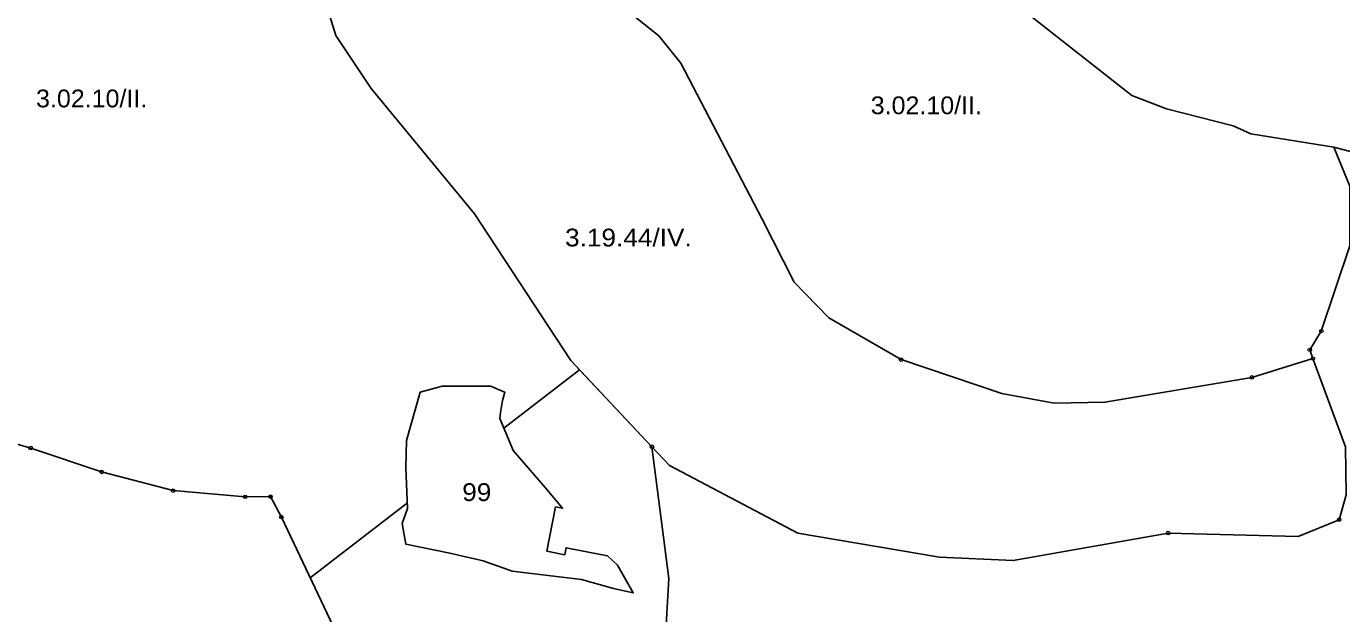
# Model space of a CAD drawing. Extents: x -650455 to -642254, y -1075222 to -1066610.
# Drawn here: x -645923 to -645184, y -1070807 to -1070477 of the extents above; entities that cross this region are included whole.
import ezdxf
from ezdxf.enums import TextEntityAlignment as Align

# ---------------------------------------------------------------- set-up
doc = ezdxf.new("R2010")
doc.units = 0
doc.header["$LTSCALE"] = 4
doc.header["$PDMODE"] = 32
doc.header["$PDSIZE"] = 2
for name, color, linetype, lineweight in [('1', 7, 'Continuous', 25), ('11', 7, 'Continuous', 13), ('12', 7, 'Continuous', 13), ('14', 7, 'Continuous', 13)]:
    doc.layers.add(name, color=color, linetype=linetype, lineweight=lineweight)
doc.layers.add('2', color=7, linetype='Continuous')

msp = doc.modelspace()

# ---------------------------------------------------------------- linework, layer by layer
at = {"layer": '1'}
for points in [[(-645696.21, -1070233.478), (-645696.21, -1070244.446), (-645693.219, -1070253.691), (-645689.807, -1070258.381), (-645677.134, -1070272.424), (-645674.491, -1070275.223), (-645637.482, -1070290.618), (-645562.376, -1070313.01), (-645530.032, -1070322.029), (-645499.088, -1070345.198), (-645474.208, -1070360.748), (-645449.328, -1070376.453), (-645424.604, -1070393.714), (-645420.219, -1070400.367), (-645417, -1070402.501), (-645403, -1070418.001), (-645378, -1070455.501), (-645302, -1070515.501), (-645282.5, -1070523), (-645245, -1070532.501), (-645235, -1070537.001), (-645188.5, -1070544.501), (-645179.5, -1070566.5)], [(-644777, -1070514), (-644832, -1070537.001), (-644888.5, -1070557.001), (-644982, -1070577.501), (-645008.5, -1070579.5), (-645087, -1070571), (-645188.5, -1070544.501), (-645235, -1070537.001), (-645245, -1070532.501), (-645282.5, -1070523), (-645302, -1070515.501), (-645378, -1070455.501), (-645403, -1070418.001), (-645417, -1070402.501), (-645420.219, -1070400.367), (-645424.604, -1070393.714), (-645449.328, -1070376.453), (-645474.208, -1070360.748)], [(-645763.626, -1070420.193), (-645769.807, -1070414.012), (-645749.009, -1070481.878), (-645729, -1070511.501), (-645671, -1070582), (-645617, -1070664.5), (-645571.435, -1070712.939), (-645562, -1070787.001), (-645566, -1070859), (-645576.5, -1070881.501), (-645600.5, -1070904.001), (-645607.5, -1070909.001), (-645646.5, -1070921.501), (-645665, -1070920), (-645678.5, -1070914.5), (-645700.5, -1070899.5), (-645723, -1070872.001), (-645779.5, -1070752.5), (-645785.632, -1070741.019), (-645799.865, -1070741.1), (-645840.313, -1070737.642), (-645880.438, -1070727.108), (-645920.242, -1070713.679), (-645927.962, -1070711.588)], [(-645749.009, -1070481.878), (-645769.807, -1070414.012)], [(-645179.5, -1070600), (-645195.5, -1070648), (-645202, -1070658.501), (-645200.205, -1070663.392), (-645234.5, -1070674.001), (-645317, -1070688), (-645345.5, -1070688.5), (-645375, -1070683.001), (-645431.5, -1070664), (-645472, -1070640.5), (-645491.5, -1070620.501), (-645509.5, -1070585.001), (-645555.128, -1070497.341), (-645567.5, -1070482), (-645607.333, -1070449.913), (-645628.962, -1070442.703), (-645656.783, -1070418.36)], [(-645607.333, -1070449.913), (-645567.5, -1070482), (-645555.128, -1070497.341), (-645509.5, -1070585.001), (-645491.5, -1070620.501), (-645472, -1070640.5), (-645431.5, -1070664), (-645375, -1070683.001), (-645345.5, -1070688.5), (-645317, -1070688), (-645234.5, -1070674.001), (-645200.205, -1070663.392), (-645182, -1070713)], [(-645181.5, -1070740), (-645185.5, -1070754), (-645208.5, -1070763.501), (-645281.5, -1070761.5), (-645368.5, -1070777), (-645410, -1070775.001), (-645489.5, -1070761.5), (-645561.5, -1070723.501), (-645571.435, -1070712.939), (-645617, -1070664.5), (-645671, -1070582), (-645729, -1070511.501), (-645749.009, -1070481.878)], [(-645566, -1070859), (-645562, -1070787.001), (-645571.435, -1070712.939), (-645561.5, -1070723.501), (-645489.5, -1070761.5), (-645410, -1070775.001), (-645368.5, -1070777), (-645281.5, -1070761.5), (-645208.5, -1070763.501), (-645185.5, -1070754), (-645181.5, -1070740), (-645182, -1070713), (-645200.205, -1070663.392), (-645202, -1070658.501), (-645195.5, -1070648), (-645179.5, -1070600), (-645179.5, -1070566.5), (-645188.5, -1070544.501), (-645087, -1070571), (-645008.5, -1070579.5), (-644982, -1070577.501), (-644888.5, -1070557.001), (-644832, -1070537.001), (-644777, -1070514)], [(-645927.962, -1070711.588), (-645920.242, -1070713.679), (-645880.438, -1070727.108), (-645840.313, -1070737.642)], [(-645840.313, -1070737.642), (-645799.865, -1070741.1), (-645785.632, -1070741.019), (-645779.5, -1070752.5), (-645723, -1070872.001)]]:
    msp.add_lwpolyline(points, dxfattribs=at)
for points in [[(-645631.348, -1070735.807), (-645621.58, -1070747.558), (-645625.53, -1070746.79), (-645630.39, -1070771.751), (-645620.35, -1070773.691), (-645619.59, -1070769.75), (-645617.65, -1070770.131), (-645601.26, -1070773.33), (-645598.31, -1070773.9), (-645596.319, -1070774.289), (-645590.68, -1070779.525), (-645581.869, -1070795.114), (-645593.052, -1070792.742), (-645611.014, -1070787.659), (-645649.987, -1070782.914), (-645666.254, -1070777.153), (-645684.894, -1070772.747), (-645709.633, -1070767.664), (-645711.667, -1070756.141), (-645708.617, -1070747.669), (-645709.633, -1070724.623), (-645709.294, -1070709.373), (-645701.5, -1070682.261), (-645689.299, -1070678.872), (-645661.848, -1070678.872), (-645660.211, -1070679.584), (-645660.21, -1070679.591), (-645655.86, -1070681.476), (-645654.054, -1070682.261), (-645655.409, -1070687.006), (-645656.426, -1070693.784), (-645656.765, -1070697.173), (-645650.141, -1070713.131), (-645650.14, -1070713.14), (-645649.309, -1070715.132)], [(-645631.348, -1070735.807), (-645649.309, -1070715.132), (-645650.14, -1070713.14), (-645650.141, -1070713.131), (-645656.765, -1070697.173), (-645656.426, -1070693.784), (-645655.409, -1070687.006), (-645654.054, -1070682.261), (-645655.86, -1070681.476), (-645660.21, -1070679.591), (-645660.211, -1070679.584), (-645661.848, -1070678.872), (-645689.299, -1070678.872), (-645701.5, -1070682.261), (-645709.294, -1070709.373), (-645709.633, -1070724.623), (-645708.617, -1070747.669), (-645711.667, -1070756.141), (-645709.633, -1070767.664), (-645684.894, -1070772.747), (-645666.254, -1070777.153), (-645649.987, -1070782.914), (-645611.014, -1070787.659), (-645593.052, -1070792.742), (-645581.869, -1070795.114), (-645590.68, -1070779.525), (-645596.319, -1070774.289), (-645598.31, -1070773.9), (-645601.26, -1070773.33), (-645617.65, -1070770.131), (-645619.59, -1070769.75), (-645620.35, -1070773.691), (-645630.39, -1070771.751), (-645625.53, -1070746.79), (-645621.58, -1070747.558)]]:
    msp.add_lwpolyline(points, close=True, dxfattribs=at)
at = {"layer": '11'}
for p, q in [((-645840.313, -1070737.642), (-645880.438, -1070727.108)), ((-645779.5, -1070752.5), (-645785.632, -1070741.019)), ((-645723, -1070872.001), (-645779.5, -1070752.5))]:
    msp.add_line(p, q, dxfattribs=at)
for points in [[(-644684, -1070421), (-644702.5, -1070450), (-644728.5, -1070479.001), (-644777, -1070514), (-644832, -1070537.001), (-644888.5, -1070557.001), (-644982, -1070577.501), (-645008.5, -1070579.5), (-645087, -1070571), (-645188.5, -1070544.501), (-645179.5, -1070566.5)], [(-645378, -1070455.501), (-645302, -1070515.501), (-645282.5, -1070523), (-645245, -1070532.501), (-645235, -1070537.001), (-645188.5, -1070544.501), (-645087, -1070571)], [(-645179.5, -1070566.5), (-645179.5, -1070600), (-645195.5, -1070648), (-645202, -1070658.501), (-645200.205, -1070663.392), (-645182, -1070713), (-645181.5, -1070740), (-645185.5, -1070754)], [(-645880.438, -1070727.108), (-645920.242, -1070713.679), (-645927.962, -1070711.588)], [(-645185.5, -1070754), (-645208.5, -1070763.501), (-645281.5, -1070761.5), (-645368.5, -1070777), (-645410, -1070775.001), (-645489.5, -1070761.5), (-645561.5, -1070723.501), (-645571.435, -1070712.939), (-645562, -1070787.001), (-645566, -1070859), (-645576.5, -1070881.501), (-645600.5, -1070904.001), (-645607.5, -1070909.001), (-645646.5, -1070921.501), (-645665, -1070920), (-645678.5, -1070914.5), (-645700.5, -1070899.5)], [(-645785.632, -1070741.019), (-645799.865, -1070741.1), (-645840.313, -1070737.642)]]:
    msp.add_lwpolyline(points, dxfattribs=at)
for p in [(-645880.438, -1070727.108), (-645840.313, -1070737.642), (-645785.632, -1070741.019), (-645779.5, -1070752.5), (-645185.5, -1070754)]:
    msp.add_point(p, dxfattribs=at)
at = {"layer": '12'}
for p, q in [((-645202, -1070658.501), (-645195.5, -1070648)), ((-645200.205, -1070663.392), (-645202, -1070658.501)), ((-645920.242, -1070713.679), (-645880.438, -1070727.108))]:
    msp.add_line(p, q, dxfattribs=at)
for points in [[(-645660.21, -1070679.591), (-645655.86, -1070681.476), (-645654.054, -1070682.261), (-645655.409, -1070687.006), (-645656.426, -1070693.784), (-645656.765, -1070697.173), (-645654.518, -1070702.587), (-645612.056, -1070669.756), (-645617, -1070664.5), (-645671, -1070582), (-645729, -1070511.501), (-645749.009, -1070481.878), (-645769.807, -1070414.012), (-645763.626, -1070420.193), (-645768.65, -1070402.889), (-645785.491, -1070380.435), (-645812.997, -1070356.859), (-645836.012, -1070342.825), (-645851.729, -1070325.985), (-645864.64, -1070297.356), (-645883.165, -1070254.133), (-645892.146, -1070237.292), (-645934.808, -1070159.546)], [(-645195.5, -1070648), (-645179.5, -1070600), (-645179.5, -1070566.5), (-645188.5, -1070544.501), (-645235, -1070537.001), (-645245, -1070532.501), (-645282.5, -1070523), (-645302, -1070515.501), (-645378, -1070455.501), (-645403, -1070418.001), (-645417, -1070402.501), (-645420.219, -1070400.367)], [(-645607.333, -1070449.913), (-645567.5, -1070482), (-645555.128, -1070497.341), (-645509.5, -1070585.001), (-645491.5, -1070620.501), (-645472, -1070640.5), (-645431.5, -1070664)], [(-645982.884, -1070639.297), (-645972.912, -1070658.757), (-645965.032, -1070672.106), (-645950.317, -1070694.38), (-645927.962, -1070711.588), (-645920.242, -1070713.679)], [(-645431.5, -1070664), (-645375, -1070683.001), (-645345.5, -1070688.5), (-645317, -1070688), (-645234.5, -1070674.001), (-645200.205, -1070663.392)], [(-645566, -1070859), (-645562, -1070787.001), (-645571.435, -1070712.939), (-645612.056, -1070669.756), (-645654.518, -1070702.587), (-645650.141, -1070713.131), (-645650.14, -1070713.14), (-645649.309, -1070715.132), (-645631.348, -1070735.807), (-645621.58, -1070747.558), (-645625.53, -1070746.79), (-645630.39, -1070771.751), (-645620.35, -1070773.691), (-645619.59, -1070769.75), (-645617.65, -1070770.131), (-645601.26, -1070773.33), (-645598.31, -1070773.9), (-645596.319, -1070774.289), (-645590.68, -1070779.525), (-645581.869, -1070795.114), (-645593.052, -1070792.742), (-645611.014, -1070787.659), (-645649.987, -1070782.914), (-645666.254, -1070777.153), (-645684.894, -1070772.747), (-645709.633, -1070767.664), (-645711.667, -1070756.141), (-645708.617, -1070747.669), (-645708.756, -1070744.522), (-645763.324, -1070786.713), (-645723, -1070872.001)], [(-645799.865, -1070741.1), (-645785.632, -1070741.019), (-645779.5, -1070752.5), (-645763.324, -1070786.713), (-645708.756, -1070744.522), (-645709.633, -1070724.623), (-645709.294, -1070709.373), (-645701.5, -1070682.261), (-645689.299, -1070678.872), (-645661.848, -1070678.872), (-645660.211, -1070679.584)], [(-645880.438, -1070727.108), (-645840.313, -1070737.642), (-645799.865, -1070741.1)]]:
    msp.add_lwpolyline(points, dxfattribs=at)
for p in [(-645195.5, -1070648), (-645202, -1070658.501), (-645431.5, -1070664), (-645200.205, -1070663.392), (-645920.242, -1070713.679), (-645880.438, -1070727.108), (-645799.865, -1070741.1)]:
    msp.add_point(p, dxfattribs=at)
at = {"layer": '14'}
for points in [[(-645787.196, -1070260.996), (-645773.285, -1070288.817), (-645748.941, -1070323.593), (-645728.075, -1070351.415), (-645712.426, -1070366.195), (-645701.993, -1070383.583), (-645674.172, -1070421.837), (-645677.649, -1070442.703), (-645688.022, -1070470.362), (-645695.5, -1070468.001), (-645711, -1070465.5), (-645712.054, -1070466.012), (-645729.814, -1070460.091), (-645741.986, -1070441.834), (-645763.626, -1070420.193), (-645769.807, -1070414.012), (-645749.009, -1070481.878), (-645729, -1070511.501), (-645671, -1070582), (-645617, -1070664.5), (-645616.574, -1070664.953), (-645612.056, -1070669.756), (-645571.435, -1070712.939)], [(-645234.5, -1070674.001), (-645317, -1070688), (-645345.5, -1070688.5), (-645375, -1070683.001), (-645431.5, -1070664), (-645472, -1070640.5), (-645491.5, -1070620.501), (-645509.5, -1070585.001), (-645555.128, -1070497.341), (-645567.5, -1070482), (-645607.333, -1070449.913)], [(-645185.5, -1070754), (-645181.5, -1070740), (-645182, -1070713), (-645200.205, -1070663.392), (-645234.5, -1070674.001)], [(-645571.435, -1070712.939), (-645561.5, -1070723.501), (-645489.5, -1070761.5), (-645410, -1070775.001), (-645368.5, -1070777), (-645281.5, -1070761.5)], [(-645281.5, -1070761.5), (-645208.5, -1070763.501), (-645185.5, -1070754)]]:
    msp.add_lwpolyline(points, dxfattribs=at)
for p in [(-645234.5, -1070674.001), (-645571.435, -1070712.939), (-645185.5, -1070754), (-645281.5, -1070761.5)]:
    msp.add_point(p, dxfattribs=at)

# ---------------------------------------------------------------- texts
at = {"layer": '2'}
for s, width, p in [('3.02.10/II.', 1.05, (-645886.055, -1070522.198)), ('3.02.10/II.', 1.05, (-645417.306, -1070526.048)), ('3.19.44/IV.', 1.1, (-645584.628, -1070600.39)), ('99', 1.1, (-645669.775, -1070743.491))]:
    msp.add_text(s, height=10, dxfattribs=dict(at, width=width)).set_placement(p, align=Align.CENTER)

doc.saveas('drawing.dxf')
